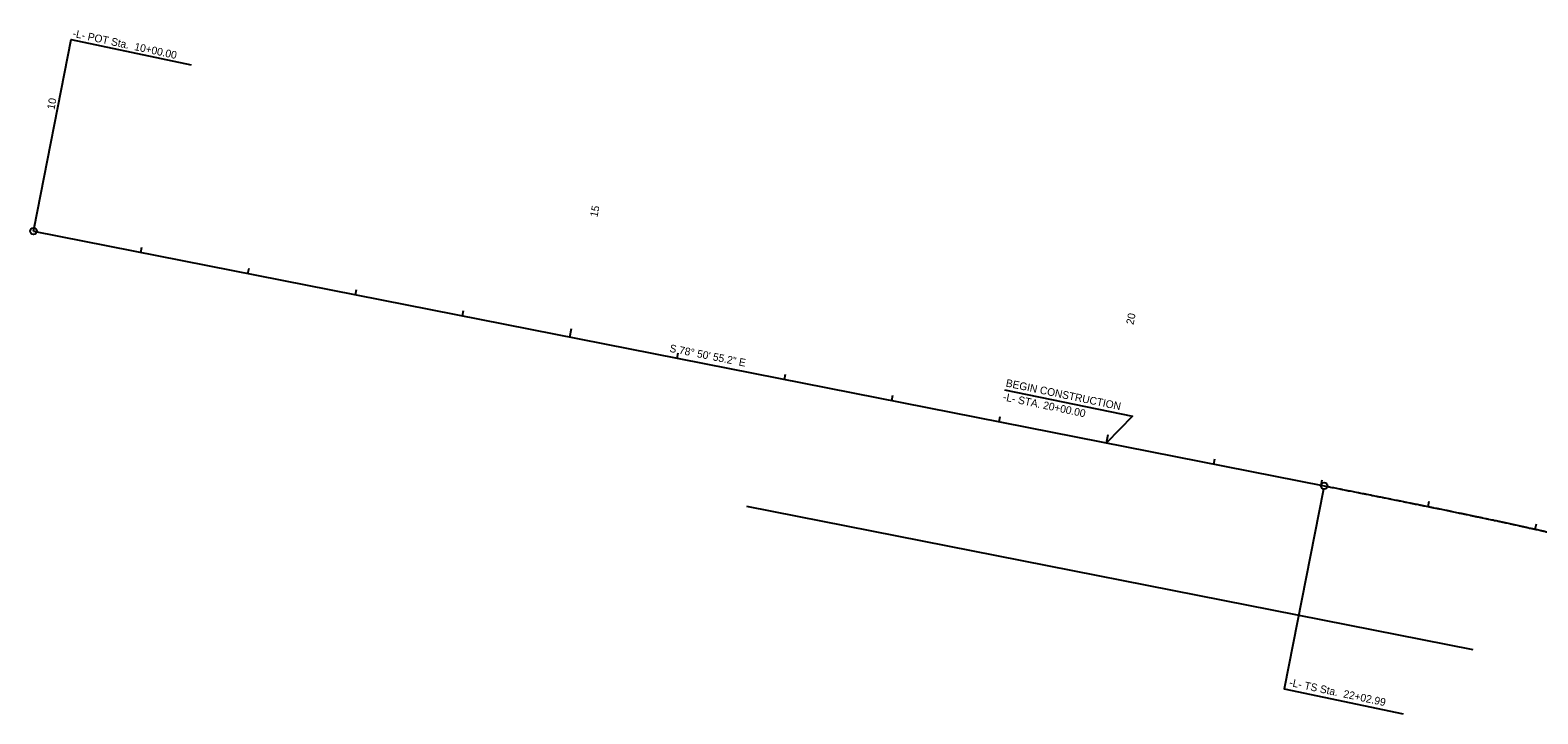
# Model space of a CAD drawing. Extents: x 1636713 to 1642889, y 841520 to 844630.
# Drawn here: x 1636713 to 1638092, y 843381 to 844006 of the extents above; entities that cross this region are included whole.
import ezdxf

# ---------------------------------------------------------------- set-up
doc = ezdxf.new("R2010")
doc.units = 0
for name, color, linetype in [('Exist 4 AWG with gnd feeder circuit in conduit', 7, 'Continuous'), ('Exist 6 AWG with gnd feeder circuit', 7, 'Continuous'), ('Exist 8 AWG with gnd feeder circuit', 7, 'Continuous'), ('Exist 8 AWG with gnd feeder circuit in conduit', 7, 'Continuous'), ('Prop 2 AWG with gnd feeder circuit in conduit', 7, 'Continuous'), ('Prop 4 AWG with gnd feeder circuit', 7, 'Continuous'), ('Prop Clearing and Grubbing', 7, 'Continuous')]:
    doc.layers.add(name, color=color, linetype=linetype)

msp = doc.modelspace()

# ---------------------------------------------------------------- linework, layer by layer
at = {"layer": 'Exist 6 AWG with gnd feeder circuit'}
for points in [[(1636716.7, 843825.4), (1636750.7, 843997.8), (1636860.5, 843974.5)], [(1637604, 843677.7), (1637721.2, 843653.4), (1637697.2, 843629.1)], [(1637895.8, 843586.9), (1637859.8, 843404.3), (1637968.7, 843381.4)]]:
    msp.add_lwpolyline(points, dxfattribs=at)
for centre in [(1636716.1, 843822.5), (1637896.4, 843589.8)]:
    msp.add_circle(centre, 3, dxfattribs=at)
at = {"layer": 'Exist 8 AWG with gnd feeder circuit'}
msp.add_line((1636716.1, 843822.5), (1637896.4, 843589.8), dxfattribs=at)
msp.add_spline([(1637896.4, 843589.8), (1637899.2, 843589.3), (1637902, 843588.7), (1637904.8, 843588.2), (1637907.5, 843587.6), (1637910.3, 843587.1), (1637913.1, 843586.5), (1637915.9, 843586), (1637918.7, 843585.4), (1637921.5, 843584.9), (1637924.2, 843584.3), (1637927, 843583.8), (1637929.8, 843583.2), (1637932.6, 843582.7), (1637935.4, 843582.1), (1637938.2, 843581.6), (1637941, 843581), (1637943.7, 843580.5), (1637946.5, 843579.9), (1637949.3, 843579.4), (1637952.1, 843578.8), (1637954.9, 843578.3), (1637957.7, 843577.7), (1637960.4, 843577.1), (1637963.2, 843576.6), (1637966, 843576), (1637968.8, 843575.5), (1637971.6, 843574.9), (1637974.3, 843574.4), (1637977.1, 843573.8), (1637979.9, 843573.2), (1637982.7, 843572.7), (1637985.5, 843572.1), (1637988.3, 843571.5), (1637991, 843571), (1637993.8, 843570.4), (1637996.6, 843569.8), (1637999.4, 843569.3), (1638002.2, 843568.7), (1638004.9, 843568.1), (1638007.7, 843567.6), (1638010.5, 843567), (1638013.3, 843566.4), (1638016.1, 843565.9), (1638018.8, 843565.3), (1638021.6, 843564.7), (1638024.4, 843564.1), (1638027.2, 843563.5), (1638029.9, 843563), (1638032.7, 843562.4), (1638035.5, 843561.8), (1638038.3, 843561.2), (1638041.1, 843560.6), (1638043.8, 843560), (1638046.6, 843559.4), (1638049.4, 843558.9), (1638052.2, 843558.3), (1638054.9, 843557.7), (1638057.7, 843557.1), (1638060.5, 843556.5), (1638063.3, 843555.9), (1638066, 843555.3), (1638068.8, 843554.7), (1638071.6, 843554.1), (1638074.3, 843553.5), (1638077.1, 843552.9), (1638079.9, 843552.3), (1638082.7, 843551.6), (1638085.4, 843551), (1638088.2, 843550.4), (1638091, 843549.8), (1638093.7, 843549.2), (1638096.5, 843548.6), (1638099.3, 843547.9), (1638102.1, 843547.3)], degree=3, dxfattribs=at)
at = {"layer": 'Prop 2 AWG with gnd feeder circuit in conduit'}
for p, q in [((1636716.1, 843822.5), (1636717.7, 843830.3)), ((1637206.7, 843725.8), (1637208.2, 843733.6)), ((1637697.2, 843629.1), (1637698.8, 843636.9))]:
    msp.add_line(p, q, dxfattribs=at)
at = {"layer": 'Prop 4 AWG with gnd feeder circuit'}
for p, q in [((1636814.2, 843803.1), (1636815.2, 843808)), ((1636912.3, 843783.8), (1636913.3, 843788.7)), ((1637010.5, 843764.5), (1637011.4, 843769.4)), ((1637108.6, 843745.1), (1637109.5, 843750)), ((1637304.8, 843706.4), (1637305.8, 843711.3)), ((1637402.9, 843687.1), (1637403.9, 843692)), ((1637501, 843667.8), (1637502, 843672.7)), ((1637599.1, 843648.4), (1637600.1, 843653.3)), ((1637795.4, 843609.7), (1637796.3, 843614.6)), ((1637893.5, 843590.4), (1637894.4, 843595.3)), ((1637991.5, 843570.9), (1637992.5, 843575.8)), ((1638089.4, 843550.2), (1638090.5, 843555))]:
    msp.add_line(p, q, dxfattribs=at)
at = {"layer": 'Prop Clearing and Grubbing'}
msp.add_line((1637368.1, 843571.2), (1638032.3, 843440.3), dxfattribs=at)

# ---------------------------------------------------------------- texts
at = {"layer": 'Exist 4 AWG with gnd feeder circuit in conduit'}
for s, p in [('10', (1636735.3, 843933.3)), ('15', (1637231.8, 843835)), ('20', (1637722, 843736.7))]:
    msp.add_text(s, height=7, rotation=78.8487, dxfattribs=at).set_placement(p)
at = {"layer": 'Exist 6 AWG with gnd feeder circuit'}
for s, rotation, p in [('-L- POT Sta.  10+00.00', 347.8675, (1636751.5, 844000.3)), ('BEGIN CONSTRUCTION', 348.2865, (1637604.8, 843680.7)), ('-L- STA. 20+00.00', 348.2865, (1637602.2, 843668)), ('-L- TS Sta.  22+02.99', 348.0462, (1637864, 843407))]:
    msp.add_text(s, height=7, rotation=rotation, dxfattribs=at).set_placement(p)
at = {"layer": 'Exist 8 AWG with gnd feeder circuit in conduit'}
msp.add_text('S 78%%d 50\' 55.2" E', height=7, rotation=348.8487, dxfattribs=at).set_placement((1637297.3, 843712.4))

doc.saveas('drawing.dxf')
